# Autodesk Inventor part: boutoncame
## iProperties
Created: 2002-07
Part Number: boutoncame
Material: Par défaut
Document SubType Name: Modélisation
Designer: robert
Control State: 0
Master: False
Checked Out: False
Shininess: 20.0
Length Units: 11269
Angle Units: 11279
Time Units: 11290
Mass Units: 11283
Length Display Precision: 3
Angle Display Precision: 2
Compacted: True
Density: 0.0
Volumn: 0.0
Area: 0.0
PropertySet Name: Model Information
Author: robert
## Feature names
1. Base1
